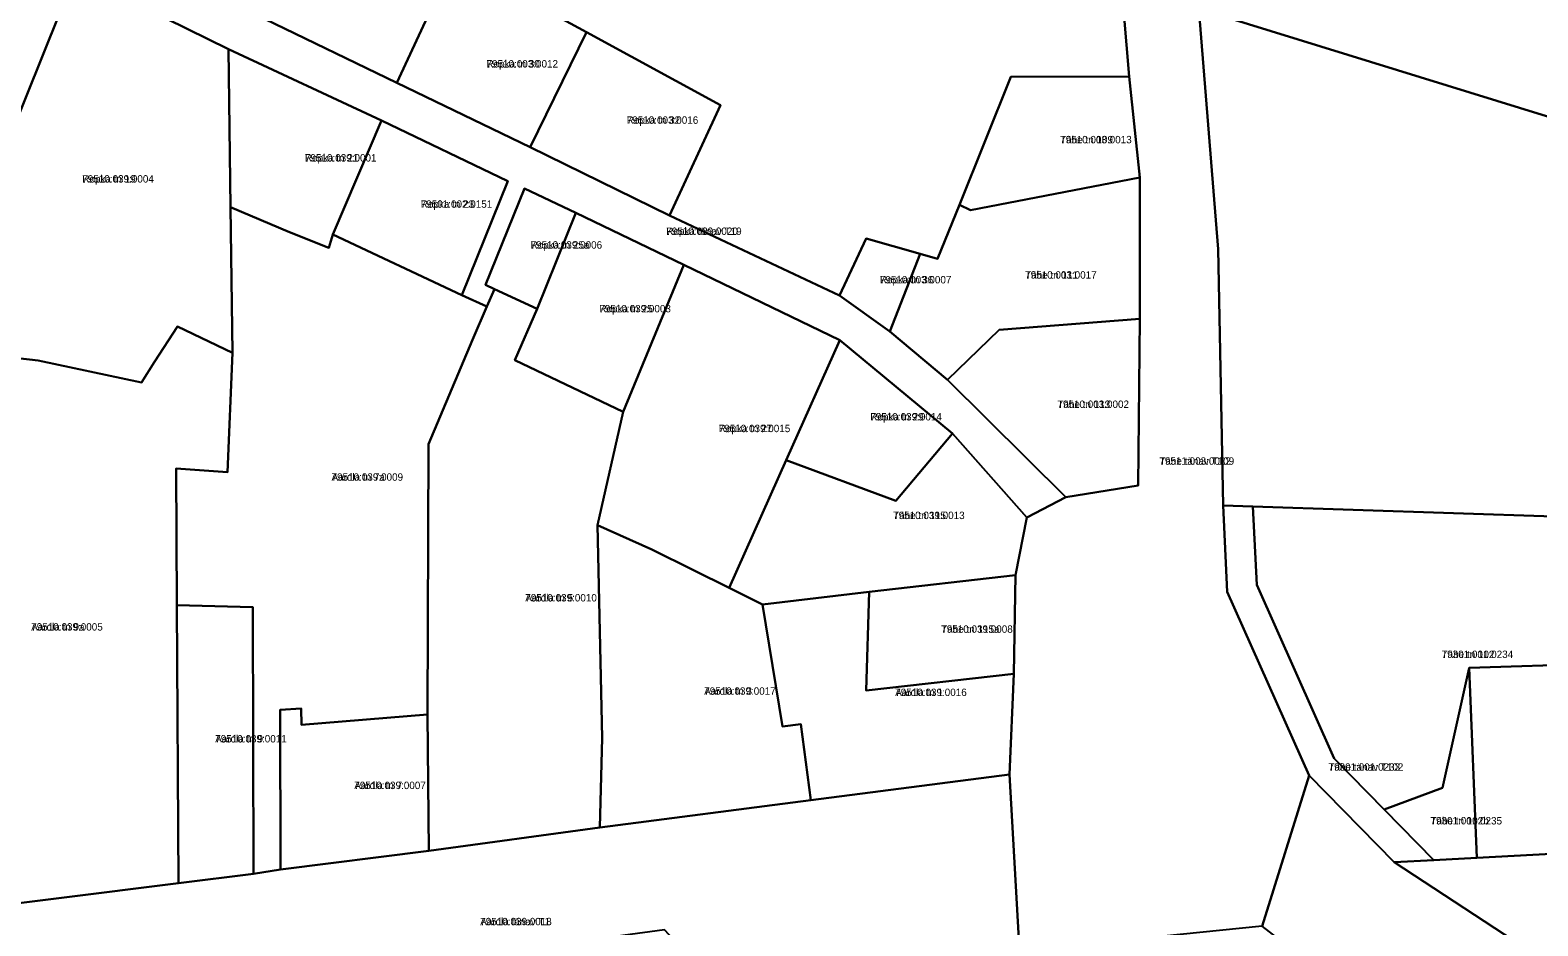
# Model space of a CAD drawing. Extents: x 643847 to 663718, y 6468443 to 6482775.
# Drawn here: x 659596.7 to 659902.3, y 6471607 to 6471788.5 of the extents above; entities that cross this region are included whole.
import ezdxf

# ---------------------------------------------------------------- set-up
doc = ezdxf.new("R2010")
doc.units = 0
for name, color, linetype in [('L_AADRESS', 7, 'Continuous'), ('PIIR', 7, 'Continuous'), ('TUNNUS', 7, 'Continuous')]:
    doc.layers.add(name, color=color, linetype=linetype)

msp = doc.modelspace()

# ---------------------------------------------------------------- linework, layer by layer
at = {"layer": 'PIIR'}
for points in [[(659726.31, 6471751), (659736.64, 6471773.34), (659709.49, 6471788.15), (659694.75, 6471796.19), (659691.87, 6471790.95), (659679.96, 6471797.09), (659670.99, 6471777.89), (659644.21, 6471790.84), (659662.42, 6471827.56), (659648.37, 6471835.94), (659644.77, 6471841.74), (659659.13, 6471870.87), (659780.42, 6471814.89), (659817.75, 6471799.3), (659819.49, 6471779.17), (659795.49, 6471779.09), (659785.04, 6471753.17), (659780.64, 6471742.22), (659777.08, 6471743.23), (659766.14, 6471746.33), (659760.77, 6471734.75)], [(660221.86, 6471788.64), (660175.78, 6471771.31), (660131.86, 6471751.61), (660040.55, 6471736.16), (659999.28, 6471741.7), (659833.61, 6471792.85), (659839.59, 6471816.09), (659870.87, 6471805.68), (659874.45, 6471803.74), (659889.69, 6471798.96), (659891.61, 6471806.68), (659966.45, 6471783.73), (660004.51, 6471774.49), (660019.14, 6471772.07), (660137.26, 6471785.98), (660171.14, 6471794.05), (660216.83, 6471817.7)], [(659636.88, 6471784.7), (659637.33, 6471752.65), (659637.73, 6471723.16), (659626.54, 6471728.45), (659621.91, 6471721.33), (659619.26, 6471717.15), (659598.34, 6471721.61), (659587.61, 6471722.81), (659576.79, 6471728.38), (659585.27, 6471748.83), (659602.7, 6471792.03), (659605.35, 6471794.44), (659609.36, 6471796.85), (659611.76, 6471797.12)], [(659670.99, 6471777.89), (659679.96, 6471797.09), (659691.87, 6471790.95), (659694.75, 6471796.19), (659709.49, 6471788.15), (659698.01, 6471764.85)], [(659817.75, 6471799.3), (659833.61, 6471792.85), (659837.53, 6471744.15), (659838.53, 6471692.21), (659839.36, 6471674.7), (659855.96, 6471637.45), (659846.41, 6471606.89), (659797.25, 6471601.92), (659795.21, 6471637.67), (659796.11, 6471658.09), (659796.4, 6471678.1), (659798.71, 6471689.75), (659806.62, 6471693.9), (659821.29, 6471696.22), (659821.65, 6471730.04), (659821.63, 6471758.67), (659819.49, 6471779.17)], [(659698.01, 6471764.85), (659709.49, 6471788.15), (659736.64, 6471773.34), (659726.31, 6471751)], [(659667.9, 6471770.22), (659658.07, 6471747.14), (659657.2, 6471744.41), (659649.27, 6471747.63), (659637.33, 6471752.65), (659636.88, 6471784.7)], [(659821.63, 6471758.67), (659787.27, 6471752.05), (659785.04, 6471753.17), (659795.49, 6471779.09), (659819.49, 6471779.17)], [(659658.07, 6471747.14), (659667.9, 6471770.22), (659693.53, 6471757.94), (659684.2, 6471734.86)], [(659821.65, 6471730.04), (659793.1, 6471727.83), (659782.64, 6471717.68), (659770.95, 6471727.43), (659777.08, 6471743.23), (659780.64, 6471742.22), (659785.04, 6471753.17), (659787.27, 6471752.05), (659821.63, 6471758.67)], [(659707.28, 6471751.51), (659699.45, 6471732.07), (659690.8, 6471736.06), (659688.98, 6471736.9), (659696.87, 6471756.43)], [(659641.98, 6471617.51), (659641.81, 6471671.58), (659626.42, 6471671.96), (659626.31, 6471699.71), (659636.69, 6471698.98), (659637.73, 6471723.16), (659637.33, 6471752.65), (659649.27, 6471747.63), (659657.2, 6471744.41), (659658.07, 6471747.14), (659684.2, 6471734.86), (659689.24, 6471732.54), (659686.38, 6471725.79), (659677.43, 6471704.61), (659677.23, 6471649.82), (659651.72, 6471647.71), (659651.63, 6471651.03), (659647.37, 6471650.79), (659647.44, 6471618.38)], [(659729.21, 6471740.97), (659716.89, 6471711.17), (659694.93, 6471721.64), (659699.45, 6471732.07), (659707.28, 6471751.51)], [(659760.77, 6471734.75), (659766.14, 6471746.33), (659777.08, 6471743.23), (659770.95, 6471727.43)], [(659729.21, 6471740.97), (659760.83, 6471725.72), (659749.94, 6471701.38), (659738.37, 6471675.52), (659731.13, 6471679.09), (659722.68, 6471683.24), (659711.72, 6471688.21), (659716.89, 6471711.17)], [(659677.48, 6471622.19), (659677.23, 6471649.82), (659677.43, 6471704.61), (659686.38, 6471725.79), (659689.24, 6471732.54), (659690.8, 6471736.06), (659699.45, 6471732.07), (659694.93, 6471721.64), (659716.89, 6471711.17), (659711.72, 6471688.21), (659712.64, 6471645.13), (659712.15, 6471626.9)], [(659821.29, 6471696.22), (659806.62, 6471693.9), (659782.64, 6471717.68), (659793.1, 6471727.83), (659821.65, 6471730.04)], [(659578.73, 6471609.63), (659572.78, 6471647), (659556.08, 6471676.78), (659582.17, 6471660.21), (659584.92, 6471658.91), (659586.79, 6471661.05), (659590.75, 6471666.39), (659591.05, 6471698.82), (659589.46, 6471704.27), (659572.4, 6471712.37), (659570.08, 6471709.81), (659576.79, 6471728.38), (659587.61, 6471722.81), (659598.34, 6471721.61), (659619.26, 6471717.15), (659621.91, 6471721.33), (659626.54, 6471728.45), (659637.73, 6471723.16), (659636.69, 6471698.98), (659626.31, 6471699.71), (659626.42, 6471671.96), (659626.74, 6471615.64)], [(659760.83, 6471725.72), (659783.66, 6471706.78), (659772.19, 6471693.14), (659749.94, 6471701.38)], [(659798.71, 6471689.75), (659796.4, 6471678.1), (659766.74, 6471674.68), (659745.14, 6471672.1), (659738.37, 6471675.52), (659749.94, 6471701.38), (659772.19, 6471693.14), (659783.66, 6471706.78)], [(659838.53, 6471692.21), (659844.54, 6471691.98), (659845.33, 6471676.1), (659861, 6471640.88), (659871.14, 6471630.58), (659881.22, 6471620.33), (659873.19, 6471619.88), (659855.96, 6471637.45), (659839.36, 6471674.7)], [(659845.33, 6471676.1), (659844.54, 6471691.98), (659905.54, 6471689.97), (659914.03, 6471660.07), (659888.38, 6471659.27), (659882.95, 6471634.96), (659871.14, 6471630.58), (659861, 6471640.88)], [(659711.72, 6471688.21), (659722.68, 6471683.24), (659731.13, 6471679.09), (659738.37, 6471675.52), (659745.14, 6471672.1), (659749.19, 6471647.4), (659752.92, 6471647.87), (659754.93, 6471632.45), (659712.15, 6471626.9), (659712.64, 6471645.13)], [(659796.11, 6471658.09), (659766.17, 6471654.68), (659766.74, 6471674.68), (659796.4, 6471678.1)], [(659745.14, 6471672.1), (659766.73, 6471674.68), (659766.17, 6471654.68), (659796.11, 6471658.09), (659795.21, 6471637.67), (659754.93, 6471632.45), (659752.92, 6471647.87), (659749.19, 6471647.4)], [(659626.74, 6471615.64), (659626.42, 6471671.96), (659641.81, 6471671.58), (659641.98, 6471617.51)], [(659889.95, 6471620.77), (659888.38, 6471659.27), (659914.03, 6471660.07), (659907.84, 6471653.26), (659915.57, 6471625.27), (659916.45, 6471622.16)], [(659882.95, 6471634.96), (659888.38, 6471659.27), (659889.95, 6471620.77), (659881.22, 6471620.33), (659871.14, 6471630.58)], [(659647.44, 6471618.38), (659647.37, 6471650.79), (659651.63, 6471651.03), (659651.72, 6471647.71), (659677.23, 6471649.82), (659677.48, 6471622.19)], [(659795.21, 6471637.67), (659797.25, 6471601.92), (659772.6, 6471598.32), (659736.31, 6471594.4), (659725.24, 6471606.19), (659701.45, 6471602.91), (659676.82, 6471599.52), (659645.89, 6471595.59), (659646.6, 6471590.65), (659620.87, 6471581.91), (659620.31, 6471584.76), (659619.1, 6471584.49), (659609.15, 6471582.53), (659606.98, 6471582.1), (659607.41, 6471580.11), (659580.87, 6471576.54), (659578.73, 6471609.63), (659626.74, 6471615.64), (659641.98, 6471617.51), (659647.44, 6471618.38), (659677.48, 6471622.19), (659712.15, 6471626.9), (659754.93, 6471632.45)], [(659846.41, 6471606.89), (659855.96, 6471637.45), (659873.19, 6471619.88), (659930.09, 6471582.62), (659950.05, 6471577.2), (659951.45, 6471565.89), (659966.86, 6471567.85), (659964.82, 6471541.72), (659932.46, 6471550.82), (659867.98, 6471573.55), (659856.17, 6471600.52), (659853.27, 6471601.63)]]:
    msp.add_lwpolyline(points, close=True, dxfattribs=at)
for points in [[(659644.21, 6471790.84), (659670.99, 6471777.89), (659698.01, 6471764.85), (659726.31, 6471751), (659760.77, 6471734.75), (659770.95, 6471727.43), (659782.64, 6471717.68), (659806.62, 6471693.9), (659798.71, 6471689.75), (659783.66, 6471706.78), (659760.83, 6471725.72), (659729.21, 6471740.97), (659707.28, 6471751.51), (659696.87, 6471756.43), (659688.98, 6471736.9), (659690.8, 6471736.06), (659689.24, 6471732.54), (659684.2, 6471734.86), (659693.53, 6471757.94), (659667.9, 6471770.22), (659636.88, 6471784.7), (659611.76, 6471797.12)], [(659602.7, 6471792.03), (659585.27, 6471748.83)], [(659905.54, 6471689.97), (659844.54, 6471691.98), (659838.53, 6471692.21), (659837.53, 6471744.15), (659833.61, 6471792.85), (659999.28, 6471741.7)], [(659930.09, 6471582.62), (659873.19, 6471619.88), (659881.22, 6471620.33), (659889.95, 6471620.77), (659916.45, 6471622.16)]]:
    msp.add_lwpolyline(points, dxfattribs=at)

# ---------------------------------------------------------------- texts
at = {"layer": 'L_AADRESS'}
for s, p in [('Ropka tn 30', (659689.19, 6471780.97)), ('Ropka tn 32', (659717.62, 6471769.57)), ('Tähe tn 109', (659805.48, 6471765.61)), ('Ropka tn 21', (659652.39, 6471761.91)), ('Ropka tn 19', (659607.26, 6471757.65)), ('Ropka tn 23', (659675.86, 6471752.54)), ('Ropka tänav T19', (659725.64, 6471747.04)), ('Ropka tn 25a', (659698.13, 6471744.26)), ('Tähe tn 111', (659798.38, 6471738.18)), ('Ropka tn 36', (659768.93, 6471737.21)), ('Ropka tn 25', (659712.07, 6471731.34)), ('Tähe tn 113', (659804.93, 6471711.97)), ('Ropka tn 27', (659736.27, 6471707.06)), ('Ropka tn 29', (659767, 6471709.43)), ('Tähe tänav T109', (659825.59, 6471700.45)), ('Aardla tn 7a', (659657.78, 6471697.21)), ('Tähe tn 115', (659771.62, 6471689.44)), ('Aardla tn 5', (659697.06, 6471672.74)), ('Aardla tn 9a', (659596.9, 6471666.84)), ('Tähe tn 115a', (659781.37, 6471666.39)), ('Tähe tn 102', (659882.81, 6471661.28)), ('Aardla tn 3', (659733.32, 6471653.83)), ('Aardla tn 1', (659772.04, 6471653.57)), ('Aardla tn 9', (659634.2, 6471644.16)), ('Tähe tänav T102', (659859.88, 6471638.43)), ('Aardla tn 7', (659662.39, 6471634.71)), ('Tähe tn 102b', (659880.55, 6471627.54)), ('Aardla tänav T1', (659687.92, 6471607.11))]:
    msp.add_text(s, height=1.5, dxfattribs=at).set_placement(p)
at = {"layer": 'TUNNUS'}
for s, p in [('79510:003:0012', (659689.19, 6471780.97)), ('79510:003:0016', (659717.62, 6471769.57)), ('79510:003:0013', (659805.48, 6471765.61)), ('79510:039:0001', (659652.39, 6471761.91)), ('79510:039:0004', (659607.26, 6471757.65)), ('79501:002:0151', (659675.86, 6471752.54)), ('79510:039:0020', (659725.64, 6471747.04)), ('79510:039:0006', (659698.13, 6471744.26)), ('79510:003:0017', (659798.38, 6471738.18)), ('79510:003:0007', (659768.93, 6471737.21)), ('79510:039:0003', (659712.07, 6471731.34)), ('79510:003:0002', (659804.93, 6471711.97)), ('79510:039:0015', (659736.27, 6471707.06)), ('79510:039:0014', (659767, 6471709.43)), ('79511:003:0022', (659825.59, 6471700.45)), ('79510:039:0009', (659657.78, 6471697.21)), ('79510:039:0013', (659771.62, 6471689.44)), ('79510:039:0010', (659697.06, 6471672.74)), ('79510:039:0005', (659596.9, 6471666.84)), ('79510:039:0008', (659781.37, 6471666.39)), ('79301:001:0234', (659882.81, 6471661.28)), ('79510:039:0017', (659733.32, 6471653.83)), ('79510:039:0016', (659772.04, 6471653.57)), ('79510:039:0011', (659634.2, 6471644.16)), ('79301:001:0233', (659859.88, 6471638.43)), ('79510:039:0007', (659662.39, 6471634.71)), ('79301:001:0235', (659880.55, 6471627.54)), ('79510:039:0018', (659687.92, 6471607.11))]:
    msp.add_text(s, height=1.5, dxfattribs=at).set_placement(p)

doc.saveas('drawing.dxf')
